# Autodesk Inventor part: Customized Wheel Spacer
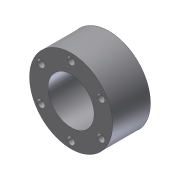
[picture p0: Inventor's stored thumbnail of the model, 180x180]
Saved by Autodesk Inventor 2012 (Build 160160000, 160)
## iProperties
Created: 2010-12
Part Number: Customized Wheel Spacer
Document SubType Name: Modeling
Designer: Alex
Density: 1 g/cm^3
Material: Default
Mass: 42.9203 g
Surface Area: 131.176 cm^2
Volume: 42.9203 cm^3
Author: Alex
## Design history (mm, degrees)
derived "Spacer, 1.600 in.ipt"
sketch "Sketch2"
  geometry: C1 r 28.575 at (0, 23.812) reference
extrude "Extrusion2" cut sketch "Sketch2" distance "d20" = 11.4046; taper "d21" = 0 deg
sketch "Sketch3"
  geometry: C1 r 28.575 at (0, -23.812) reference
extrude "Extrusion3" cut sketch "Sketch3" distance "d22" = 3.175; taper "d23" = 0 deg
body "Solid2"
feature "Solid1::Spacer, 1.600 in.ipt" dims "d19" = 10
tag "TaggingFeature1"
